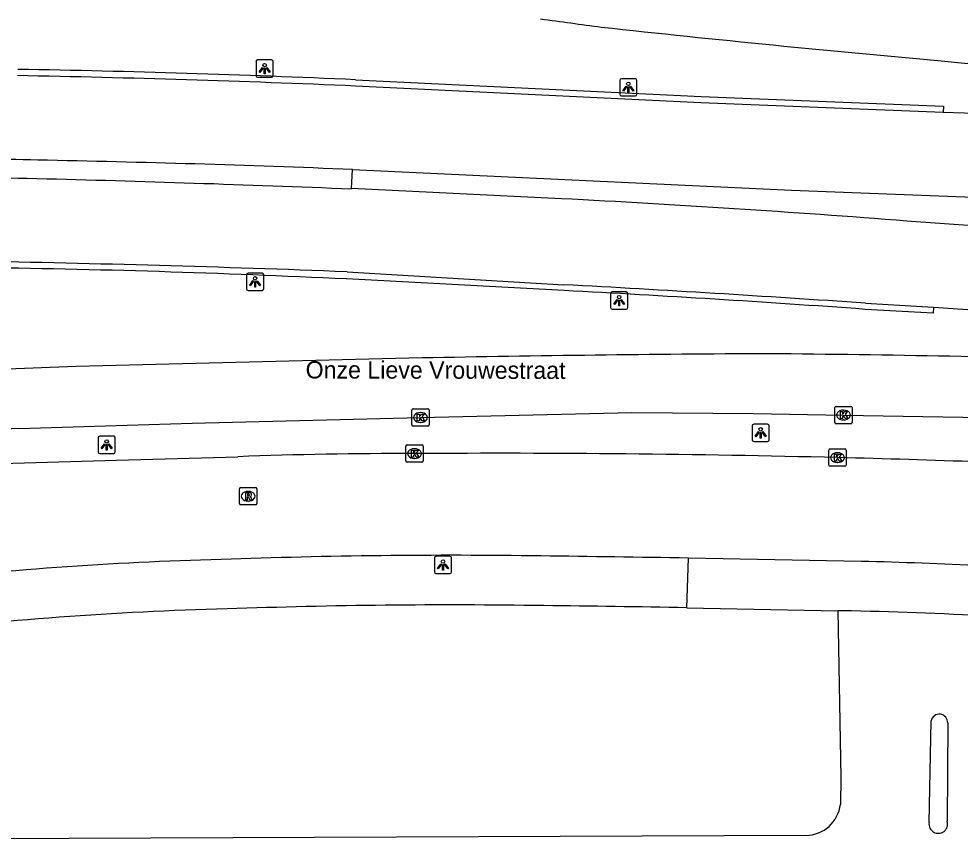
# Model space of a CAD drawing. Extents: x 161243 to 161752, y 384138 to 384885.
# Drawn here: x 161377.2 to 161431.6, y 384836.7 to 384884.2 of the extents above; entities that cross this region are included whole.
import ezdxf

# ---------------------------------------------------------------- set-up
doc = ezdxf.new("R2010")
doc.units = 0
for name, color, linetype in [('IMGEO_Berm_gesloten', 7, 'Continuous'), ('IMGEO_Kolk', 7, 'Continuous'), ('IMGEO_Lichtpunt', 7, 'Continuous'), ('IMGEO_Muur', 7, 'Continuous'), ('IMGEO_Openbare_ruimte_label', 7, 'Continuous'), ('IMGEO_Rijbaan_lokaal_open', 7, 'Continuous'), ('IMGEO_Rijbaan_regionaal_gesloten', 7, 'Continuous'), ('IMGEO_Rioolput', 7, 'Continuous'), ('IMGEO_Voetpad_open', 7, 'Continuous')]:
    doc.layers.add(name, color=color, linetype=linetype)

msp = doc.modelspace()

# ---------------------------------------------------------------- linework, layer by layer
at = {"layer": 'IMGEO_Berm_gesloten'}
msp.add_lwpolyline([(161396.378, 384874.413), (161396.448, 384875.513)], dxfattribs=at)
at = {"layer": 'IMGEO_Kolk'}
for p, q in [((161399.869, 384860.759), (161399.869, 384861.611)), ((161399.944, 384861.685), (161400.796, 384861.685)), ((161400.357, 384861.465), (161400.382, 384861.465)), ((161400.87, 384861.611), (161400.87, 384860.759)), ((161424.312, 384860.903), (161424.312, 384861.755)), ((161424.387, 384861.829), (161425.239, 384861.829)), ((161424.8, 384861.609), (161424.825, 384861.609)), ((161425.313, 384861.755), (161425.313, 384860.903)), ((161400.38, 384860.905), (161400.355, 384860.905)), ((161425.239, 384860.829), (161424.387, 384860.829)), ((161424.823, 384861.049), (161424.798, 384861.049)), ((161400.796, 384860.685), (161399.944, 384860.685)), ((161399.53, 384858.675), (161399.53, 384859.527)), ((161399.605, 384859.601), (161400.457, 384859.601)), ((161400.018, 384859.381), (161400.043, 384859.381)), ((161400.531, 384859.527), (161400.531, 384858.675)), ((161423.968, 384858.44), (161423.968, 384859.292)), ((161424.043, 384859.366), (161424.895, 384859.366)), ((161424.456, 384859.146), (161424.481, 384859.146)), ((161424.969, 384859.292), (161424.969, 384858.44)), ((161400.457, 384858.601), (161399.605, 384858.601)), ((161400.041, 384858.821), (161400.016, 384858.821)), ((161424.895, 384858.366), (161424.043, 384858.366)), ((161424.479, 384858.586), (161424.454, 384858.586))]:
    msp.add_line(p, q, dxfattribs=at)
for points in [[(161399.869, 384860.759), (161399.869, 384861.611)], [(161399.944, 384861.685), (161400.796, 384861.685)], [(161400.19, 384861.385), (161400.313, 384861.385), (161400.313, 384861.234), (161400.443, 384861.385), (161400.607, 384861.385), (161400.461, 384861.234), (161400.614, 384860.985), (161400.462, 384860.985), (161400.377, 384861.149), (161400.313, 384861.082), (161400.313, 384860.985), (161400.19, 384860.985), (161400.19, 384861.385)], [(161400.87, 384861.611), (161400.87, 384860.759)], [(161424.312, 384860.903), (161424.312, 384861.755)], [(161424.387, 384861.829), (161425.239, 384861.829)], [(161424.633, 384861.529), (161424.756, 384861.529), (161424.756, 384861.378), (161424.886, 384861.529), (161425.05, 384861.529), (161424.904, 384861.378), (161425.057, 384861.129), (161424.905, 384861.129), (161424.82, 384861.293), (161424.756, 384861.226), (161424.756, 384861.129), (161424.633, 384861.129), (161424.633, 384861.529)], [(161425.313, 384861.755), (161425.313, 384860.903)], [(161425.239, 384860.829), (161424.387, 384860.829)], [(161400.796, 384860.685), (161399.944, 384860.685)], [(161399.53, 384858.675), (161399.53, 384859.527)], [(161399.605, 384859.601), (161400.457, 384859.601)], [(161399.851, 384859.301), (161399.974, 384859.301), (161399.974, 384859.15), (161400.104, 384859.301), (161400.268, 384859.301), (161400.122, 384859.15), (161400.275, 384858.901), (161400.123, 384858.901), (161400.038, 384859.065), (161399.974, 384858.998), (161399.974, 384858.901), (161399.851, 384858.901), (161399.851, 384859.301)], [(161400.531, 384859.527), (161400.531, 384858.675)], [(161423.968, 384858.44), (161423.968, 384859.292)], [(161424.043, 384859.366), (161424.895, 384859.366)], [(161424.969, 384859.292), (161424.969, 384858.44)], [(161400.457, 384858.601), (161399.605, 384858.601)], [(161424.289, 384859.066), (161424.412, 384859.066), (161424.412, 384858.915), (161424.542, 384859.066), (161424.706, 384859.066), (161424.56, 384858.915), (161424.713, 384858.666), (161424.561, 384858.666), (161424.476, 384858.83), (161424.412, 384858.763), (161424.412, 384858.666), (161424.289, 384858.666), (161424.289, 384859.066)], [(161424.895, 384858.366), (161424.043, 384858.366)]]:
    msp.add_lwpolyline(points, dxfattribs=at)
for centre, start, end in [((161399.946, 384861.609), 91.552, 178.448), ((161399.946, 384861.609), 91.552, 178.448), ((161400.794, 384861.609), 1.552, 88.448), ((161400.794, 384861.609), 1.552, 88.448), ((161424.389, 384861.753), 91.552, 178.448), ((161424.389, 384861.753), 91.552, 178.448), ((161425.237, 384861.753), 1.552, 88.448), ((161425.237, 384861.753), 1.552, 88.448), ((161424.389, 384860.905), 181.552, 268.448), ((161424.389, 384860.905), 181.552, 268.448), ((161425.237, 384860.905), 271.552, 358.448), ((161425.237, 384860.905), 271.552, 358.448), ((161399.946, 384860.761), 181.552, 268.448), ((161399.946, 384860.761), 181.552, 268.448), ((161400.794, 384860.761), 271.552, 358.448), ((161400.794, 384860.761), 271.552, 358.448), ((161399.607, 384859.525), 91.552, 178.448), ((161399.607, 384859.525), 91.552, 178.448), ((161400.455, 384859.525), 1.552, 88.448), ((161400.455, 384859.525), 1.552, 88.448), ((161424.045, 384859.29), 91.552, 178.448), ((161424.045, 384859.29), 91.552, 178.448), ((161424.893, 384859.29), 1.552, 88.448), ((161424.893, 384859.29), 1.552, 88.448), ((161399.607, 384858.677), 181.552, 268.448), ((161399.607, 384858.677), 181.552, 268.448), ((161400.455, 384858.677), 271.552, 358.448), ((161400.455, 384858.677), 271.552, 358.448), ((161424.045, 384858.442), 181.552, 268.448), ((161424.045, 384858.442), 181.552, 268.448), ((161424.893, 384858.442), 271.552, 358.448), ((161424.893, 384858.442), 271.552, 358.448)]:
    msp.add_arc(centre, 0.0765, start, end, dxfattribs=at)
for centre, major_axis, ratio, start_param, end_param in [((161400.356, 384861.185), (-0.387, 0.002), 0.722429, 4.712389, 7.853982), ((161400.381, 384861.185), (-0.39, 0.002), 0.717154, 1.570796, 4.712389), ((161424.799, 384861.329), (-0.387, 0.002), 0.722429, 4.712389, 7.853982), ((161424.824, 384861.329), (-0.39, 0.002), 0.717154, 1.570796, 4.712389), ((161400.017, 384859.101), (-0.387, 0.002), 0.722429, 4.712389, 7.853982), ((161400.042, 384859.101), (-0.39, 0.002), 0.717154, 1.570796, 4.712389), ((161424.455, 384858.866), (-0.387, 0.002), 0.722429, 4.712389, 7.853982), ((161424.48, 384858.866), (-0.39, 0.002), 0.717154, 1.570796, 4.712389)]:
    msp.add_ellipse(centre, major_axis=major_axis, ratio=ratio, start_param=start_param, end_param=end_param, dxfattribs=at)
at = {"layer": 'IMGEO_Lichtpunt'}
for p, q in [((161390.87, 384881.748), (161390.87, 384880.941)), ((161390.87, 384881.748), (161390.87, 384880.941)), ((161391.772, 384881.843), (161390.964, 384881.843)), ((161391.772, 384881.843), (161390.964, 384881.843)), ((161391.866, 384880.941), (161391.866, 384881.748)), ((161391.866, 384880.941), (161391.866, 384881.748)), ((161390.964, 384880.847), (161391.772, 384880.847)), ((161390.964, 384880.847), (161391.772, 384880.847)), ((161411.884, 384880.663), (161411.884, 384879.856)), ((161411.884, 384880.663), (161411.884, 384879.856)), ((161412.786, 384880.758), (161411.978, 384880.758)), ((161412.786, 384880.758), (161411.978, 384880.758)), ((161412.88, 384879.856), (161412.88, 384880.663)), ((161412.88, 384879.856), (161412.88, 384880.663)), ((161411.978, 384879.762), (161412.786, 384879.762)), ((161411.978, 384879.762), (161412.786, 384879.762)), ((161391.219, 384869.522), (161390.411, 384869.522)), ((161391.219, 384869.522), (161390.411, 384869.522)), ((161390.317, 384869.427), (161390.317, 384868.62)), ((161390.317, 384869.427), (161390.317, 384868.62)), ((161391.313, 384868.62), (161391.313, 384869.427)), ((161391.313, 384868.62), (161391.313, 384869.427)), ((161390.411, 384868.526), (161391.219, 384868.526)), ((161390.411, 384868.526), (161391.219, 384868.526)), ((161412.255, 384868.438), (161411.447, 384868.438)), ((161412.255, 384868.438), (161411.447, 384868.438)), ((161411.353, 384868.343), (161411.353, 384867.536)), ((161411.353, 384868.343), (161411.353, 384867.536)), ((161412.349, 384867.536), (161412.349, 384868.343)), ((161412.349, 384867.536), (161412.349, 384868.343)), ((161411.447, 384867.442), (161412.255, 384867.442)), ((161411.447, 384867.442), (161412.255, 384867.442)), ((161420.431, 384860.799), (161419.623, 384860.799)), ((161420.431, 384860.799), (161419.623, 384860.799)), ((161419.529, 384860.704), (161419.529, 384859.897)), ((161419.529, 384860.704), (161419.529, 384859.897)), ((161420.525, 384859.897), (161420.525, 384860.704)), ((161420.525, 384859.897), (161420.525, 384860.704)), ((161381.745, 384860.006), (161381.745, 384859.199)), ((161381.745, 384860.006), (161381.745, 384859.199)), ((161382.647, 384860.101), (161381.839, 384860.101)), ((161382.647, 384860.101), (161381.839, 384860.101)), ((161382.741, 384859.199), (161382.741, 384860.006)), ((161382.741, 384859.199), (161382.741, 384860.006)), ((161419.623, 384859.803), (161420.431, 384859.803)), ((161419.623, 384859.803), (161420.431, 384859.803)), ((161381.839, 384859.105), (161382.647, 384859.105)), ((161381.839, 384859.105), (161382.647, 384859.105)), ((161402.077, 384853.165), (161401.269, 384853.165)), ((161402.077, 384853.165), (161401.269, 384853.165)), ((161401.175, 384853.07), (161401.175, 384852.263)), ((161401.175, 384853.07), (161401.175, 384852.263)), ((161402.171, 384852.263), (161402.171, 384853.07)), ((161402.171, 384852.263), (161402.171, 384853.07)), ((161401.269, 384852.169), (161402.077, 384852.169)), ((161401.269, 384852.169), (161402.077, 384852.169))]:
    msp.add_line(p, q, dxfattribs=at)
for points in [[(161391.244, 384881.412), (161391.283, 384881.384), (161391.095, 384881.122), (161391.057, 384881.149), (161391.244, 384881.412)], [(161391.346, 384881.364), (161391.393, 384881.364), (161391.393, 384881.042), (161391.346, 384881.042), (161391.346, 384881.364)], [(161391.456, 384881.384), (161391.494, 384881.411), (161391.681, 384881.149), (161391.642, 384881.121), (161391.456, 384881.384)], [(161412.258, 384880.327), (161412.297, 384880.299), (161412.109, 384880.037), (161412.071, 384880.064), (161412.258, 384880.327)], [(161412.36, 384880.279), (161412.407, 384880.279), (161412.407, 384879.957), (161412.36, 384879.957), (161412.36, 384880.279)], [(161412.47, 384880.299), (161412.508, 384880.326), (161412.695, 384880.064), (161412.656, 384880.036), (161412.47, 384880.299)], [(161390.691, 384869.091), (161390.73, 384869.063), (161390.542, 384868.801), (161390.504, 384868.828), (161390.691, 384869.091)], [(161390.793, 384869.043), (161390.84, 384869.043), (161390.84, 384868.721), (161390.793, 384868.721), (161390.793, 384869.043)], [(161390.903, 384869.063), (161390.941, 384869.09), (161391.128, 384868.828), (161391.089, 384868.8), (161390.903, 384869.063)], [(161411.727, 384868.007), (161411.766, 384867.979), (161411.578, 384867.717), (161411.54, 384867.744), (161411.727, 384868.007)], [(161411.829, 384867.959), (161411.876, 384867.959), (161411.876, 384867.637), (161411.829, 384867.637), (161411.829, 384867.959)], [(161411.939, 384867.979), (161411.977, 384868.006), (161412.164, 384867.744), (161412.125, 384867.716), (161411.939, 384867.979)], [(161419.903, 384860.368), (161419.942, 384860.34), (161419.754, 384860.078), (161419.716, 384860.105), (161419.903, 384860.368)], [(161420.005, 384860.32), (161420.052, 384860.32), (161420.052, 384859.998), (161420.005, 384859.998), (161420.005, 384860.32)], [(161420.115, 384860.34), (161420.153, 384860.367), (161420.34, 384860.105), (161420.301, 384860.077), (161420.115, 384860.34)], [(161382.119, 384859.67), (161382.158, 384859.642), (161381.97, 384859.38), (161381.932, 384859.407), (161382.119, 384859.67)], [(161382.221, 384859.622), (161382.268, 384859.622), (161382.268, 384859.3), (161382.221, 384859.3), (161382.221, 384859.622)], [(161382.331, 384859.642), (161382.369, 384859.669), (161382.556, 384859.407), (161382.517, 384859.379), (161382.331, 384859.642)], [(161401.549, 384852.734), (161401.588, 384852.706), (161401.4, 384852.444), (161401.362, 384852.471), (161401.549, 384852.734)], [(161401.651, 384852.686), (161401.698, 384852.686), (161401.698, 384852.364), (161401.651, 384852.364), (161401.651, 384852.686)], [(161401.761, 384852.706), (161401.799, 384852.733), (161401.986, 384852.471), (161401.947, 384852.443), (161401.761, 384852.706)]]:
    msp.add_lwpolyline(points, dxfattribs=at)
for centre in [(161391.369, 384881.546), (161412.383, 384880.461), (161390.816, 384869.225), (161411.852, 384868.141), (161420.028, 384860.502), (161382.244, 384859.804), (161401.674, 384852.868)]:
    msp.add_circle(centre, 0.0994, dxfattribs=at)
for centre, start, end in [((161390.964, 384881.748), 90, 180), ((161390.964, 384881.748), 90, 180), ((161391.772, 384881.748), 0, 90), ((161391.772, 384881.748), 0, 90), ((161390.964, 384880.941), 180, 270), ((161390.964, 384880.941), 180, 270), ((161391.772, 384880.941), 270, 0), ((161391.772, 384880.941), 270, 360), ((161411.978, 384880.663), 90, 180), ((161411.978, 384880.663), 90, 180), ((161412.786, 384880.663), 0, 90), ((161412.786, 384880.663), 0, 90), ((161411.978, 384879.856), 180, 270), ((161411.978, 384879.856), 180, 270), ((161412.786, 384879.856), 270, 0), ((161412.786, 384879.856), 270, 360), ((161390.411, 384869.427), 90, 180), ((161390.411, 384869.427), 90, 180), ((161391.219, 384869.427), 0, 90), ((161391.219, 384869.427), 0, 90), ((161390.411, 384868.62), 180, 270), ((161390.411, 384868.62), 180, 270), ((161391.219, 384868.62), 270, 0), ((161391.219, 384868.62), 270, 360), ((161411.447, 384868.343), 90, 180), ((161411.447, 384868.343), 90, 180), ((161412.255, 384868.343), 0, 90), ((161412.255, 384868.343), 0, 90), ((161411.447, 384867.536), 180, 270), ((161411.447, 384867.536), 180, 270), ((161412.255, 384867.536), 270, 0), ((161412.255, 384867.536), 270, 360), ((161419.623, 384860.704), 90, 180), ((161419.623, 384860.704), 90, 180), ((161420.431, 384860.704), 0, 90), ((161420.431, 384860.704), 0, 90), ((161381.839, 384860.006), 90, 180), ((161381.839, 384860.006), 90, 180), ((161382.647, 384860.006), 0, 90), ((161382.647, 384860.006), 0, 90), ((161419.623, 384859.897), 180, 270), ((161419.623, 384859.897), 180, 270), ((161420.431, 384859.897), 270, 0), ((161420.431, 384859.897), 270, 360), ((161381.839, 384859.199), 180, 270), ((161381.839, 384859.199), 180, 270), ((161382.647, 384859.199), 270, 0), ((161382.647, 384859.199), 270, 360), ((161401.269, 384853.07), 90, 180), ((161401.269, 384853.07), 90, 180), ((161402.077, 384853.07), 0, 90), ((161402.077, 384853.07), 0, 90), ((161401.269, 384852.263), 180, 270), ((161401.269, 384852.263), 180, 270), ((161402.077, 384852.263), 270, 0), ((161402.077, 384852.263), 270, 360)]:
    msp.add_arc(centre, 0.0946, start, end, dxfattribs=at)
at = {"layer": 'IMGEO_Muur'}
for points in [[(161396.622, 384880.697), (161416.599, 384879.724), (161430.582, 384879.17), (161430.576, 384878.809)], [(161430.576, 384878.809), (161416.576, 384879.372), (161396.624, 384880.335)], [(161396.128, 384869.603), (161408.651, 384868.856)], [(161408.674, 384868.514), (161396.106, 384869.189)], [(161430.006, 384867.558), (161429.986, 384867.212), (161426.061, 384867.434)], [(161426.089, 384867.788), (161430.006, 384867.558)]]:
    msp.add_lwpolyline(points, dxfattribs=at)
for centre, radius, start, end in [((161360.347, 384018.847), 862.252, 87.5887, 88.887689), ((161364.968, 384168.913), 712.488, 87.453653, 89.02337), ((161353.792, 383752.535), 1117.87, 87.82956, 88.940907), ((161366.124, 384239.814), 630.088, 87.272613, 89.244774), ((161345.268, 383691.064), 1179.497, 86.07093, 86.919602), ((161366.347, 384046.597), 823.006, 85.839219, 87.052017)]:
    msp.add_arc(centre, radius, start, end, dxfattribs=at)
at = {"layer": 'IMGEO_Rijbaan_lokaal_open'}
for points in [[(161367.605, 384858.404), (161368.837, 384858.406), (161375.071, 384858.518), (161376.817, 384858.54), (161382.819, 384858.727), (161389.811, 384858.92)], [(161425.84, 384852.876), (161415.851, 384853.066)], [(161424.74, 384850.021), (161424.486, 384850.026)], [(161424.486, 384850.026), (161424.652, 384840.397), (161424.63, 384838.837)], [(161429.756, 384837.785), (161429.876, 384843.664)], [(161430.832, 384843.545), (161430.808, 384837.857)], [(161422.646, 384837.044), (161346.934, 384836.734), (161343.397, 384836.71)]]:
    msp.add_lwpolyline(points, dxfattribs=at)
for centre, radius, start, end in [((161399.283, 384612.69), 246.412, 89.82618, 92.20307), ((161404.857, 384090.179), 768.938, 88.538497, 90.359605), ((161409.91, 384242.247), 616.79, 87.883288, 88.647413), ((161402.103, 384494.168), 359.056, 89.16361, 92.11351), ((161386.107, 383046.091), 1807.219, 89.056972, 89.326703), ((161393.635, 384656.082), 196.956, 91.38895, 96.92269), ((161420.258, 384621.05), 231.893, 86.88694, 88.62061), ((161420.534, 384619.185), 230.874, 86.82982, 88.9562), ((161430.349, 384843.564), 0.483, 357.798, 168.011), ((161422.624, 384839.063), 2.019, 270.6375, 353.5726), ((161430.29, 384837.703), 0.54, 171.3037, 16.5268)]:
    msp.add_arc(centre, radius, start, end, dxfattribs=at)
at = {"layer": 'IMGEO_Rijbaan_regionaal_gesloten'}
for points in [[(161450.063, 384878.208), (161447.842, 384878.263), (161430.576, 384878.809)], [(161396.448, 384875.513), (161421.817, 384874.322)], [(161396.378, 384874.413), (161396.376, 384874.375)], [(161408.521, 384873.825), (161396.378, 384874.413)], [(161483.247, 384868.441), (161468.458, 384869.592), (161434.47, 384872.112), (161428.475, 384872.536)], [(161430.006, 384867.558), (161443.875, 384866.611), (161466.286, 384864.875), (161467.476, 384864.787)], [(161400.465, 384864.626), (161380.485, 384864.14), (161371.481, 384863.79)], [(161377.167, 384860.545), (161387.181, 384860.85), (161400.37, 384861.185), (161412.583, 384861.466), (161419.609, 384861.421), (161424.813, 384861.329), (161442.031, 384861.03), (161444.26, 384860.941), (161465.688, 384860.125), (161467.892, 384860.1)]]:
    msp.add_lwpolyline(points, dxfattribs=at)
for centre, radius, start, end in [((161485.028, 385441.523), 562.698, 262.06157, 262.4217), ((161522.97, 385913.464), 1035.815, 263.784203, 264.88777), ((161485.876, 385451.672), 572.569, 264.46728, 265.37126), ((161364.076, 384169.149), 707.051, 88.850593, 89.95007), ((161360.34, 383972.576), 903.658, 87.71, 88.863795), ((161364.659, 384191.885), 683.222, 88.863699, 90.344595), ((161351.836, 383797.467), 1077.829, 87.63163, 88.597948), ((161491.73, 386549.721), 1676.857, 267.610477, 268.158438), ((161366.737, 384071.908), 803.005, 85.590531, 87.017288), ((161428.458, 383401.66), 1463.234, 90.312717, 91.096195), ((161406.32, 383510.609), 1354.337, 88.514869, 89.401281), ((161380.192, 384729.631), 130.949, 91.32351, 94.15355)]:
    msp.add_arc(centre, radius, start, end, dxfattribs=at)
at = {"layer": 'IMGEO_Rioolput'}
for p, q in [((161389.918, 384856.212), (161389.918, 384857.064)), ((161389.993, 384857.138), (161390.845, 384857.138)), ((161390.919, 384857.064), (161390.919, 384856.212)), ((161390.406, 384856.918), (161390.431, 384856.918)), ((161390.845, 384856.138), (161389.993, 384856.138)), ((161390.429, 384856.358), (161390.404, 384856.358))]:
    msp.add_line(p, q, dxfattribs=at)
for points in [[(161389.918, 384856.212), (161389.918, 384857.064)], [(161389.993, 384857.138), (161390.845, 384857.138)], [(161390.919, 384857.064), (161390.919, 384856.212)], [(161390.507, 384856.836), (161390.255, 384856.838), (161390.255, 384856.438)], [(161390.255, 384856.438), (161390.379, 384856.438), (161390.379, 384856.6), (161390.39, 384856.6)], [(161390.433, 384856.757), (161390.379, 384856.757), (161390.379, 384856.676)], [(161390.379, 384856.676), (161390.431, 384856.676)], [(161390.437, 384856.571), (161390.508, 384856.438), (161390.648, 384856.438), (161390.583, 384856.564)], [(161390.845, 384856.138), (161389.993, 384856.138)]]:
    msp.add_lwpolyline(points, dxfattribs=at)
for centre, radius, start, end in [((161389.995, 384857.062), 0.0765, 91.552, 178.448), ((161389.995, 384857.062), 0.0765, 91.552, 178.448), ((161390.843, 384857.062), 0.0765, 1.552, 88.448), ((161390.843, 384857.062), 0.0765, 1.552, 88.448), ((161390.389, 384856.547), 0.0533, 26.0293, 88.6989), ((161390.415, 384856.865), 0.19, 274.7715, 282.9687), ((161390.439, 384856.661), 0.0964, 77.0061, 93.1865), ((161390.453, 384856.718), 0.0378, 276.6634, 79.6772), ((161390.506, 384856.726), 0.109, 350.3612, 89.416), ((161390.504, 384856.726), 0.112, 277.5842, 350.9817), ((161390.488, 384856.511), 0.108, 29.5134, 73.7905), ((161389.995, 384856.214), 0.0765, 181.552, 268.448), ((161389.995, 384856.214), 0.0765, 181.552, 268.448), ((161390.843, 384856.214), 0.0765, 271.552, 358.448), ((161390.843, 384856.214), 0.0765, 271.552, 358.448)]:
    msp.add_arc(centre, radius, start, end, dxfattribs=at)
for centre, major_axis, ratio, start_param, end_param in [((161390.405, 384856.638), (-0.387, 0.002), 0.722429, 4.712389, 7.853982), ((161390.43, 384856.638), (-0.39, 0.002), 0.717154, 1.570796, 4.712389)]:
    msp.add_ellipse(centre, major_axis=major_axis, ratio=ratio, start_param=start_param, end_param=end_param, dxfattribs=at)
at = {"layer": 'IMGEO_Voetpad_open'}
for points in [[(161415.756, 384850.198), (161415.851, 384853.066)], [(161415.756, 384850.198), (161424.486, 384850.026)]]:
    msp.add_lwpolyline(points, dxfattribs=at)
for centre, radius, start, end in [((161394.536, 384645.004), 205.193, 91.49034, 96.91223), ((161402.135, 384485.386), 364.971, 89.15875, 92.03128), ((161386.834, 383143.384), 1707.059, 89.029208, 89.306544)]:
    msp.add_arc(centre, radius, start, end, dxfattribs=at)

# ---------------------------------------------------------------- texts
at = {"layer": 'IMGEO_Openbare_ruimte_label'}
msp.add_text('Onze Lieve Vrouwestraat', height=1, rotation=359.8854, dxfattribs=at).set_placement((161393.737, 384863.441))

doc.saveas('drawing.dxf')
